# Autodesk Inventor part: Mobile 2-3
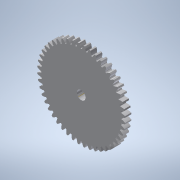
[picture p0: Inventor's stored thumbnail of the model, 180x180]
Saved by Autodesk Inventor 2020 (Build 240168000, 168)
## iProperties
Created: 2002-01
Part Number: Mobile 2-3
Material: Plastique ABS
Document SubType Name: Modélisation
Designer: Philippe
Mass: 0.0576148 g
Surface Area: 2.09657 cm^2
Volume: 0.0543536 cm^3
Density: 1.06 g/cm^3
Appearance: Lisse - Blanc
Shininess: 20.0
Angle Display Precision: 2
Document Length Units: 11269
Document Angle Units: 11279
Document Time Units: 11290
Document Mass Units: 11283
Document Length Units Precision: 3
Document Angle Units Precision: 2
Density: 0.0
Volumn: 0.0
Area: 0.0
PropertySet Name: Model Information
Control State: 0
Master: False
Checked Out: False
Author: Philippe
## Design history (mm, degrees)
sketch "Esquisse1"
  geometry: L1 (0, 0)-(5, 0); L2 (5, 0)-(5, 0.7); L3 (5, 0.7)-(1.4, 0.7); L4 (1.4, 0.7)-(1.4, 2); L5 (1.4, 2)-(0, 2); L6 (0, 2)-(0, 0)
  constraints: 12 end point, 4 parallel, 1 horizontal, 1 perpendicular, 1 other
  dimensions: "d0" = 0.7 distance of L1.end L2.end; "d1" = 2 distance between parallel lines of L5 L1; "d2" = 2.8 diameter of L4.end L6; "d3" = 10 diameter of L2 L6
revolve "Révolution1" sketch "Esquisse1" stored, may be unused: angle "d4" = 90 deg
sketch "Esquisse2"
  geometry: C1 r 5 at (0, 0) reference; C2 r 0.5 at (0, 0)
  constraints: 1 centre point, 1 coincident
  dimensions: "d5" = 1 diameter of C2
extrude "Extrusion1" cut sketch "Esquisse2" extent not by distance; stored distance "d6" = 10; taper "d7" = 0 deg
sketch "Esquisse3"
  geometry: A1 r 0.95 centre (0, 0) between (0.063, 0.948) and (-0.063, 0.948); A2 r 0.406 centre (-0.521, 1.002) between (-0.116, 0.998) and (-0.332, 1.36); A3 r 1.4 centre (0, 0) between (-0.332, 1.36) and (0.332, 1.36) reference; A4 r 0.406 centre (0.521, 1.002) between (0.332, 1.36) and (0.116, 0.998); A5 r 0.05 centre (-0.066, 0.998) between (-0.116, 0.998) and (-0.063, 0.948); A6 r 0.05 centre (0.066, 0.998) between (0.063, 0.948) and (0.116, 0.998)
  constraints: 12 point on circle, 4 centre point, 4 tangent, 1 equal radius
  dimensions: "d10" = 0.05 radius of A5
extrude "Extrusion2" cut sketch "Esquisse3" distance "d11" = 1.3; taper "d12" = 0 deg
node "Axe de construction1"
pattern_circular "Réseau circulaire1" dims angle "d15" = 360 deg
sketch "Esquisse4"
  geometry: A1 r 4.55 centre (0, 0) between (0.04, 4.55) and (-0.04, 4.55); A2 r 1.642 centre (-1.681, 4.186) between (-0.089, 4.588) and (-0.251, 4.994); A3 r 1.642 centre (1.681, 4.186) between (0.251, 4.994) and (0.089, 4.588); A4 r 0.05 centre (-0.04, 4.6) between (-0.089, 4.588) and (-0.04, 4.55); A5 r 0.05 centre (0.04, 4.6) between (0.04, 4.55) and (0.089, 4.588); A6 r 5 centre (0, 0) between (0.251, 4.994) and (-0.251, 4.994)
  constraints: 12 point on circle, 6 centre point, 4 tangent, 1 equal radius, 3 other
  dimensions: "d18" = 0.05 radius of A4
extrude "Extrusion3" cut sketch "Esquisse4" extent not by distance; stored distance "d19" = 1.3; taper "d20" = 0 deg
node "Solide1"
node "Corps solides"
node "Corps surfaciques"
pattern_circular "Réseau circulaire2" dims angle "d23" = 360 deg
